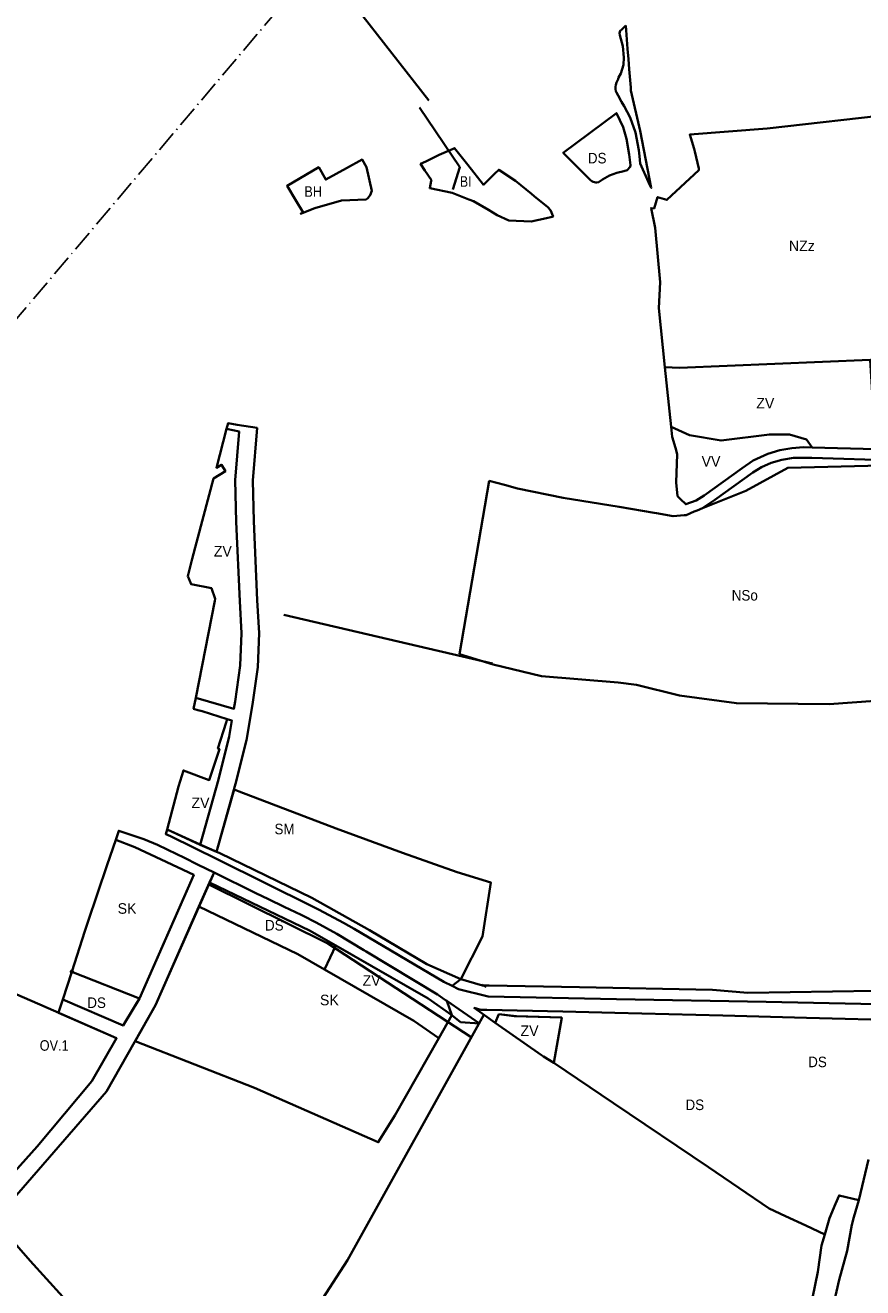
# Model space of a CAD drawing. Extents: x -650276 to -642489, y -1074311 to -1066658.
# Drawn here: x -646170 to -645218, y -1071706 to -1070271 of the extents above; entities that cross this region are included whole.
import ezdxf

# ---------------------------------------------------------------- set-up
doc = ezdxf.new("R2010")
doc.units = 0
doc.header["$LTSCALE"] = 4.8
doc.header["$PDMODE"] = 32
doc.header["$PDSIZE"] = 2.4
doc.linetypes.add('DOT_DASHED', pattern=[7.7, 5, -1.2, 0.3, -1.2])
for name, color, linetype, lineweight in [('1', 7, 'Continuous', 35), ('11', 7, 'Continuous', 35), ('15', 7, 'Continuous', 35), ('18', 7, 'Continuous', 35), ('2', 7, 'Continuous', 35), ('20', 7, 'Continuous', 35), ('24', 7, 'Continuous', 35), ('40', 7, 'Continuous', 35), ('45', 7, 'Continuous', 35), ('46', 7, 'Continuous', 35), ('54', 7, 'Continuous', 35), ('55', 7, 'Continuous', 53), ('56', 7, 'Continuous', 35)]:
    doc.layers.add(name, color=color, linetype=linetype, lineweight=lineweight)
doc.layers.add('62', color=7, linetype='Continuous')
doc.layers.add('63', color=7, linetype='Continuous')

msp = doc.modelspace()

# ---------------------------------------------------------------- linework, layer by layer
at = {"layer": '1'}
msp.add_lwpolyline([(-645862.66, -1070469.5), (-645853.98, -1070483.81), (-645856.87, -1070485.24), (-645840.59, -1070479), (-645810.44, -1070470.17), (-645782.57, -1070469.22), (-645780.38, -1070467.64), (-645777.8, -1070464.4), (-645776.04, -1070459.38), (-645782.13, -1070432.59), (-645786.9, -1070423.81), (-645804.58, -1070433.53), (-645828.24, -1070446.54), (-645836.32, -1070432.55), (-645872.35, -1070453.55)], close=True, dxfattribs=at)
at = {"layer": '11'}
msp.add_lwpolyline([(-646066.165, -1071422.155), (-646153.5, -1071383.85), (-646208.577, -1071360.044), (-646241.68, -1071416.887), (-646258.487, -1071439.265), (-646275.615, -1071460.886), (-646289.976, -1071477.514), (-646330.914, -1071521.11), (-646324, -1071535), (-646217.978, -1071613.552), (-646211.407, -1071606.247), (-646156.471, -1071545.166), (-646094.063, -1071471.007)], close=True, dxfattribs=at)
at = {"layer": '15'}
for points in [[(-645487.361, -1070271.37), (-645491.94, -1070275.85), (-645491.94, -1070275.85), (-645493.8, -1070277.67), (-645494.57, -1070280.34), (-645494.12, -1070282.52), (-645490.79, -1070294.93), (-645489.31, -1070307.77), (-645490.03, -1070316.27), (-645493.05, -1070326.11), (-645495.44, -1070330.67), (-645496.12, -1070332.34), (-645497.83, -1070336.16), (-645498.75, -1070338.98), (-645499.01, -1070340.96), (-645499.09, -1070343.91), (-645498.74, -1070345.87), (-645498, -1070347.74), (-645496.02, -1070351.15), (-645491.97, -1070358.14), (-645488.99, -1070362.96)], [(-645487.361, -1070271.37), (-645491.94, -1070275.85), (-645491.94, -1070275.85), (-645493.8, -1070277.67), (-645494.57, -1070280.34), (-645494.12, -1070282.52), (-645490.79, -1070294.93), (-645489.31, -1070307.77), (-645490.03, -1070316.27), (-645493.05, -1070326.11), (-645495.44, -1070330.67), (-645496.12, -1070332.34), (-645497.83, -1070336.16), (-645498.75, -1070338.98), (-645499.01, -1070340.96), (-645499.09, -1070343.91), (-645498.74, -1070345.87), (-645498, -1070347.74), (-645496.02, -1070351.15), (-645491.97, -1070358.14)], [(-645458.32, -1070455.91), (-645471, -1070391), (-645481.67, -1070345.39), (-645481.65, -1070342.07), (-645483.34, -1070321.17), (-645484.27, -1070309.7), (-645485.21, -1070298.03), (-645487.361, -1070271.37)], [(-645483.34, -1070321.17), (-645484.27, -1070309.7), (-645485.21, -1070298.03), (-645487.361, -1070271.37)], [(-645482.16, -1070375.96), (-645476.12, -1070393.13), (-645472.61, -1070413.13), (-645471.87, -1070419.96), (-645470.99, -1070428.07), (-645461.32, -1070449.31), (-645458.32, -1070455.91), (-645471, -1070391), (-645481.67, -1070345.39), (-645481.65, -1070342.07), (-645483.34, -1070321.17)], [(-645491.97, -1070358.14), (-645488.99, -1070362.96), (-645482.16, -1070375.96)], [(-645488.99, -1070362.96), (-645482.16, -1070375.96), (-645476.12, -1070393.13), (-645472.61, -1070413.13), (-645471.87, -1070419.96), (-645470.99, -1070428.07), (-645461.32, -1070449.31), (-645458.32, -1070455.91)], [(-646197.398, -1071620.579), (-646077.593, -1071482.499), (-646021.674, -1071384.575), (-645964.396, -1071254.314), (-645955.342, -1071233.725), (-645973.324, -1071224.925), (-645989.7, -1071216.91), (-645997.62, -1071213.03), (-646019.41, -1071202.36), (-646035.06, -1071195.87), (-646063.59, -1071186.33), (-646067.097, -1071196.699), (-646045.462, -1071204.917), (-646015.387, -1071218.854), (-645978.403, -1071236.481), (-646040.084, -1071376.813), (-646058.719, -1071407.796), (-646127.301, -1071378.036), (-646131.79, -1071391.83), (-646132.229, -1071393.179), (-646066.165, -1071422.155), (-646094.063, -1071471.007), (-646156.471, -1071545.166), (-646211.407, -1071606.247)], [(-645701.44, -1071372.25), (-645782.32, -1071323.5), (-645784.92, -1071321.93), (-645815.65, -1071303.41), (-645839.37, -1071290.6), (-645854.1, -1071282.93), (-645856.26, -1071281.91), (-645875.48, -1071272.81), (-645893.41, -1071264.04), (-645907.62, -1071257.08), (-645955.342, -1071233.725), (-645960.34, -1071245.09), (-645846, -1071300), (-645712, -1071377), (-645712, -1071377)], [(-645712, -1071377), (-645685.098, -1071395.824), (-645690.677, -1071379.721)]]:
    msp.add_lwpolyline(points, dxfattribs=at)
for points in [[(-645911.345, -1070788.463), (-645906.373, -1070728.716), (-645929.077, -1070725.068), (-645939.27, -1070723.43), (-645940.955, -1070729.799), (-645926.784, -1070732.812), (-645931.369, -1070787.913), (-645930.036, -1070835.367), (-645926.084, -1070925.481), (-645923.919, -1070961.855), (-645925.626, -1070998.754), (-645931.24, -1071039.686), (-645932.635, -1071047.688), (-645976.17, -1071035.39), (-645978.58, -1071047.68), (-645973.77, -1071049.17), (-645968.97, -1071050.66), (-645940.25, -1071059.59), (-645934.978, -1071061.119), (-645938.15, -1071079.311), (-645950.283, -1071128.057), (-645970.966, -1071202.169), (-645952.419, -1071210.117), (-645930.943, -1071133.161), (-645918.57, -1071083.449), (-645911.474, -1071042.764), (-645905.69, -1071000.578), (-645903.891, -1070961.723), (-645906.11, -1070924.449), (-645910.048, -1070834.649)], [(-645694.15, -1071357.83), (-645684.785, -1071362.539), (-645674.947, -1071355.071), (-645713.428, -1071337.765), (-645778.69, -1071299.362), (-645844.079, -1071262.487), (-645948.761, -1071211.885), (-645967, -1071204), (-646008.714, -1071184.746), (-646010.14, -1071190.08), (-646004.65, -1071192.55), (-645951.118, -1071219.11), (-645843.45, -1071272.53), (-645835.76, -1071276.35), (-645808.13, -1071290.78), (-645795.97, -1071297.93), (-645694.15, -1071357.83)]]:
    msp.add_lwpolyline(points, close=True, dxfattribs=at)
msp.add_arc((-645538.107, -1071148.434), 277.076, 233.87926, 236.5888, dxfattribs=at)
at = {"layer": '18'}
for points in [[(-645926.81, -1071141.595), (-645932.502, -1071139.426), (-645952.419, -1071210.117), (-645948.761, -1071211.885)], [(-645678.86, -1071233.58), (-645741.09, -1071211.36), (-645816.47, -1071183.63), (-645926.81, -1071141.595)], [(-645948.761, -1071211.885), (-645844.079, -1071262.487), (-645778.69, -1071299.362), (-645713.428, -1071337.765), (-645674.947, -1071355.071)], [(-645674.947, -1071355.071), (-645650.09, -1071306.433), (-645640.737, -1071244.963), (-645678.86, -1071233.58)]]:
    msp.add_lwpolyline(points, dxfattribs=at)
at = {"layer": '2'}
msp.add_lwpolyline([(-645594.769, -1070494.065), (-645577.47, -1070490.3), (-645571.13, -1070488.89), (-645569.97, -1070488.3), (-645572.86, -1070481.41), (-645575.7, -1070477.77), (-645591.49, -1070465.19), (-645594.62, -1070462.7), (-645612.77, -1070447.82), (-645631.63, -1070435.3), (-645636.42, -1070439.93), (-645648.9, -1070452.38), (-645666.99, -1070429.58), (-645682.02, -1070410.65), (-645683.52, -1070411.71), (-645699.33, -1070418.25), (-645714.74, -1070425.84), (-645720.48, -1070428.75), (-645715.56, -1070436.27), (-645708.28, -1070447.28), (-645708.42, -1070447.94), (-645710.14, -1070456.31), (-645684.78, -1070461.52), (-645665.6, -1070469.04), (-645660.29, -1070471.12), (-645643.4, -1070481.02), (-645633.35, -1070486.91), (-645620.22, -1070493)], close=True, dxfattribs=at)
at = {"layer": '20'}
for points in [[(-645990.48, -1071263.958), (-645978.403, -1071236.481), (-646015.387, -1071218.854), (-646045.462, -1071204.917), (-646067.097, -1071196.699), (-646076.713, -1071225.138)], [(-646076.713, -1071225.138), (-646098.66, -1071290.03), (-646102.011, -1071300.326), (-646117.031, -1071346.48)], [(-646117.031, -1071346.48), (-646040.084, -1071376.813), (-645990.48, -1071263.958)]]:
    msp.add_lwpolyline(points, dxfattribs=at)
msp.add_lwpolyline([(-645699.825, -1071422.134), (-645728.105, -1071402.346), (-645859.986, -1071326.563), (-645972.422, -1071272.568), (-646021.674, -1071384.575), (-646044.948, -1071425.333), (-645909.13, -1071478.56), (-645768.62, -1071540.17), (-645749.631, -1071509.908)], close=True, dxfattribs=at)
msp.add_point((-646117.031, -1071346.48), dxfattribs=at)
at = {"layer": '24'}
for points in [[(-645497.81, -1070370.93), (-645497.81, -1070370.93), (-645490.19, -1070386.97), (-645486.54, -1070400.38), (-645483.29, -1070417.99), (-645482.62, -1070423.93), (-645481.93, -1070430.04), (-645482.18, -1070432.13), (-645485.67, -1070435.7), (-645489.34, -1070437.05), (-645497.33, -1070438.82), (-645505.88, -1070441.74), (-645513.81, -1070446.24), (-645517.44, -1070449.23), (-645517.95, -1070449.45), (-645520.4, -1070449.87), (-645521.41, -1070449.84), (-645522.95, -1070449.61), (-645524.42, -1070449.16), (-645525.75, -1070448.41), (-645527.34, -1070447.1), (-645558.36, -1070416.1)], [(-645829.706, -1071343.963), (-645816.714, -1071316.828), (-645846, -1071300), (-645960.34, -1071245.09), (-645972.422, -1071272.568), (-645859.986, -1071326.563)], [(-646045.393, -1071385.64), (-646040.084, -1071376.813), (-646117.031, -1071346.48), (-646127.301, -1071378.036), (-646058.719, -1071407.796)], [(-645675.177, -1071403.922), (-645675.177, -1071403.922), (-645653.742, -1071405.36), (-645690.677, -1071379.721), (-645685.098, -1071395.824)]]:
    msp.add_lwpolyline(points, close=True, dxfattribs=at)
for points in [[(-645179.18, -1070765.86), (-645275.8, -1070762.66), (-645296.51, -1070762.52), (-645309.78, -1070764.88), (-645321.9, -1070768.47), (-645333.12, -1070773.33), (-645342.94, -1070779.31), (-645385.99, -1070810.35), (-645400.05, -1070819.84), (-645351, -1070800), (-645303, -1070774), (-645182, -1070771)], [(-645204.341, -1071368.19), (-645348.55, -1071370.559), (-645388.619, -1071366.991), (-645539.738, -1071364.092), (-645642.431, -1071362.259), (-645650.28, -1071362.07), (-645674.947, -1071355.071), (-645684.785, -1071362.539), (-645677.58, -1071366.16), (-645643.56, -1071374.75), (-645497.84, -1071377.53), (-645327.76, -1071380.76), (-645166.34, -1071384.07)], [(-645164.76, -1071401.79), (-645281.92, -1071398.82), (-645376.87, -1071396.41), (-645499.65, -1071393.3), (-645558.9, -1071391.8), (-645645.368, -1071389.96), (-645651.93, -1071389.82), (-645659.6, -1071387.71), (-645647.727, -1071396.036), (-645635.795, -1071404.403), (-645631.44, -1071394.9), (-645614.201, -1071396.844), (-645560.11, -1071398.7), (-645569.07, -1071449.88), (-645501.37, -1071495.68), (-645393.34, -1071568.75), (-645324.17, -1071615.53), (-645324.17, -1071615.53), (-645305.78, -1071624.13), (-645282.54, -1071634.997), (-645261.094, -1071645.025), (-645255.662, -1071626.67), (-645248.786, -1071610.383), (-645244.81, -1071600.61), (-645222.48, -1071606.08), (-645222.48, -1071606.08), (-645211.27, -1071560.01)], [(-645222.48, -1071606.08), (-645244.81, -1071600.61), (-645248.786, -1071610.383), (-645255.662, -1071626.67)], [(-645222.48, -1071606.08), (-645244.81, -1071600.61), (-645248.786, -1071610.383), (-645255.662, -1071626.67)], [(-645339.904, -1072462.677), (-645347.551, -1072443.527), (-645347.677, -1072391.355), (-645346.62, -1072330.914), (-645343.458, -1072278.998), (-645339.908, -1072235.158), (-645335.367, -1072185.207), (-645325.498, -1072102.789), (-645309.01, -1071998.147), (-645285.617, -1071875.733), (-645244.798, -1071696.585), (-645235.793, -1071663.703), (-645230.436, -1071634.261), (-645227.905, -1071625.277), (-645222.48, -1071606.08)], [(-645339.904, -1072462.677), (-645347.551, -1072443.527), (-645347.677, -1072391.355), (-645346.62, -1072330.914), (-645343.458, -1072278.998), (-645339.908, -1072235.158), (-645335.367, -1072185.207), (-645325.498, -1072102.789), (-645309.01, -1071998.147), (-645285.617, -1071875.733), (-645244.798, -1071696.585), (-645235.793, -1071663.703), (-645230.436, -1071634.261), (-645227.905, -1071625.277), (-645222.48, -1071606.08)], [(-645255.662, -1071626.67), (-645261.094, -1071645.025), (-645264.841, -1071657.687), (-645269.077, -1071687.396), (-645274.868, -1071717.176), (-645286.175, -1071761.228), (-645300.076, -1071820.179), (-645313.153, -1071883.081), (-645326.343, -1071952.807)], [(-645255.662, -1071626.67), (-645261.094, -1071645.025), (-645264.841, -1071657.687), (-645269.077, -1071687.396), (-645274.868, -1071717.176), (-645286.175, -1071761.228), (-645300.076, -1071820.179), (-645313.153, -1071883.081)]]:
    msp.add_lwpolyline(points, dxfattribs=at)
at = {"layer": '40'}
for points in [[(-645442.836, -1070659.455), (-645426.34, -1070660.33), (-645209.41, -1070651.2), (-645206.7, -1070694.76), (-645204.66, -1070718.51), (-645203.13, -1070749.36), (-645202.96, -1070752.89), (-645275.236, -1070750.954), (-645282, -1070742), (-645301, -1070736), (-645324, -1070736), (-645379, -1070743), (-645415, -1070737), (-645435.711, -1070727.497)], [(-645932.635, -1071047.688), (-645931.24, -1071039.686), (-645925.626, -1070998.754), (-645923.919, -1070961.855), (-645926.084, -1070925.481), (-645930.036, -1070835.367), (-645931.369, -1070787.913), (-645926.784, -1070732.812), (-645940.955, -1070729.799), (-645952.65, -1070773.98), (-645946.81, -1070770.47), (-645942.3, -1070777.96), (-645955.86, -1070786.21), (-645980.01, -1070877.28), (-645985.28, -1070897.13), (-645981.48, -1070906.35), (-645958.21, -1070910.84), (-645954.01, -1070922.8), (-645954.492, -1070925.251), (-645976.17, -1071035.39)], [(-645970.966, -1071202.169), (-645950.283, -1071128.057), (-645938.15, -1071079.311), (-645934.978, -1071061.119), (-645940.25, -1071059.59), (-645941.45, -1071063.3), (-645950.96, -1071092.8), (-645949.21, -1071093.62), (-645960.66, -1071128.71), (-645990.14, -1071117.76), (-645995.74, -1071136.22), (-646008.714, -1071184.746)], [(-645712, -1071377), (-645816.714, -1071316.828), (-645829.706, -1071343.963), (-645728.105, -1071402.346), (-645699.825, -1071422.134), (-645685.098, -1071395.824)], [(-645583.18, -1071441.3), (-645580.947, -1071442.658), (-645569.07, -1071449.88), (-645560.11, -1071398.7), (-645611.58, -1071397.14), (-645631.44, -1071394.9), (-645635.795, -1071404.403)]]:
    msp.add_lwpolyline(points, close=True, dxfattribs=at)
at = {"layer": '45'}
msp.add_lwpolyline([(-645275.236, -1070750.954), (-645285.11, -1070750.69), (-645298.41, -1070751.48), (-645312.2, -1070753.77), (-645325.82, -1070757.94), (-645342.41, -1070765.76), (-645354.98, -1070774.28), (-645398.04, -1070805.44), (-645407.37, -1070810.95), (-645419.18, -1070815.44), (-645424.969, -1070809.563), (-645428.39, -1070806.09), (-645430, -1070790.68), (-645428.73, -1070758.67), (-645430.84, -1070751.43), (-645434.53, -1070738.77), (-645435.711, -1070727.497), (-645415, -1070737), (-645379, -1070743), (-645324, -1070736), (-645301, -1070736), (-645282, -1070742)], close=True, dxfattribs=at)
at = {"layer": '46'}
for points in [[(-645023.048, -1070595.033), (-645014.277, -1070543.11), (-645004.327, -1070461.264), (-645001.312, -1070412.099), (-645003.03, -1070365.427), (-645003.102, -1070365.432), (-645006.86, -1070365.38), (-645179.26, -1070371.74), (-645326.62, -1070388.32), (-645414.65, -1070395.37), (-645409.38, -1070411.41), (-645408.66, -1070414.62), (-645404.34, -1070433.93), (-645404.4, -1070435.88), (-645440.61, -1070469.53), (-645451.226, -1070466.394), (-645455.09, -1070479.21), (-645458.46, -1070478.86), (-645454.02, -1070501.52), (-645448.36, -1070563), (-645449.82, -1070592.72), (-645442.834, -1070659.455)], [(-645442.834, -1070659.455), (-645426.34, -1070660.33), (-645209.41, -1070651.2)]]:
    msp.add_lwpolyline(points, dxfattribs=at)
at = {"layer": '54'}
for p, q in [((-645875.986, -1070940.86), (-645638.682, -1070996.266)), ((-645650.559, -1071361.544), (-645646.066, -1071363.608))]:
    msp.add_line(p, q, dxfattribs=at)
for points in [[(-645903.547, -1070057.381), (-645879.191, -1070130.665), (-645848.973, -1070180.543), (-645834.684, -1070241.324), (-645795.429, -1070249.201), (-645711.259, -1070356.569)], [(-645721.753, -1070364.565), (-645675.805, -1070432.543), (-645683.821, -1070457.746)], [(-645961.323, -1071247.326), (-645825.908, -1071314.509), (-645661.944, -1071421.517)], [(-645648.577, -1071395.44), (-645803.784, -1071674.386), (-645877, -1071788), (-645965, -1071892)], [(-646336.784, -1071524.232), (-646218.737, -1071612.767), (-646164.374, -1071674.897), (-645904.456, -1071961.331), (-645718.199, -1072151.712), (-645526.944, -1072343.922), (-645538, -1072384), (-645459, -1072440), (-645389, -1072483), (-645335, -1072526), (-645287, -1072569), (-645227, -1072617), (-645139.573, -1072694.628), (-645084.365, -1072788.086)]]:
    msp.add_lwpolyline(points, dxfattribs=at)
at = {"layer": '55', "linetype": 'DOT_DASHED', "lineweight": 25}
msp.add_line((-646590, -1071090), (-645744.292, -1070089.84), dxfattribs=at)
at = {"layer": '56'}
for points in [[(-645100.268, -1070771.946), (-645143, -1070770), (-645161, -1070770), (-645182, -1070771), (-645303, -1070774), (-645351, -1070800), (-645400.05, -1070819.84), (-645406.09, -1070822.34), (-645409.52, -1070823.76), (-645418.67, -1070827.72), (-645421.09, -1070827.89), (-645433.49, -1070828.76), (-645452.31, -1070825.52), (-645455.184, -1070825.042)], [(-645642.52, -1070788.7), (-645676.292, -1070985.89), (-645637.94, -1070997.4), (-645583.18, -1071010.7), (-645495.87, -1071017.81)], [(-645455.184, -1070825.042), (-645494.82, -1070818.45), (-645558.3, -1070808), (-645610.25, -1070797.55), (-645625, -1070793.5), (-645642.52, -1070788.7)], [(-645495.87, -1071017.81), (-645475.01, -1071020.72), (-645426.38, -1071032.8), (-645361.54, -1071041.54), (-645255.93, -1071042.36), (-645203.66, -1071038.81), (-645193.24, -1071037.31), (-645186.18, -1071030.83), (-645180.72, -1071028.86), (-645178.73, -1070972.35), (-645167.47, -1070975.2), (-645134.973, -1070977.077), (-645134.973, -1070977.077), (-645130.749, -1070959.561)]]:
    msp.add_lwpolyline(points, dxfattribs=at)

# ---------------------------------------------------------------- texts
at = {"layer": '62'}
for s, width, p in [('DS', 0.95, (-645530.386, -1070428.148)), ('BH', 0.9, (-645852.646, -1070466.101)), ('SM', 0.95, (-645886.606, -1071190.345)), ('DS', 0.95, (-645897.407, -1071299.717)), ('DS', 0.95, (-646099.407, -1071387.717)), ('OV.1', 0.9, (-646153.486, -1071436.306)), ('DS', 0.95, (-645279.957, -1071454.984)), ('DS', 0.95, (-645419.407, -1071503.717))]:
    msp.add_text(s, height=12, dxfattribs=dict(at, width=width)).set_placement(p)
for s, p in [('ZV', (-645955.588, -1070874.768)), ('ZV', (-645980.931, -1071160.591)), ('SK', (-646064.883, -1071280.659)), ('ZV', (-645786.398, -1071362.507)), ('SK', (-645834.883, -1071384.659)), ('ZV', (-645606.931, -1071419.591))]:
    msp.add_text(s, height=12, dxfattribs=at).set_placement(p)
at = {"layer": '63'}
for s, width, p in [('BI', 0.85, (-645675.657, -1070454.713)), ('NSo', 0.95, (-645366.866, -1070924.823))]:
    msp.add_text(s, height=12, dxfattribs=dict(at, width=width)).set_placement(p)
for s, p in [('NZz', (-645301.866, -1070527.823)), ('ZV', (-645338.931, -1070706.591)), ('VV', (-645401.075, -1070772.614))]:
    msp.add_text(s, height=12, dxfattribs=at).set_placement(p)

doc.saveas('drawing.dxf')
